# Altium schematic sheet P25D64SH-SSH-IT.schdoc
size 127 x 101 mm
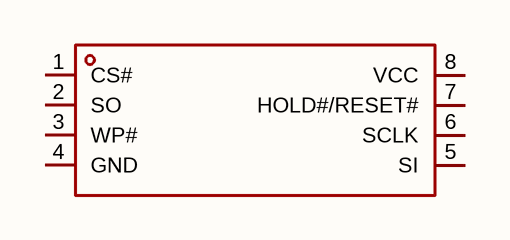
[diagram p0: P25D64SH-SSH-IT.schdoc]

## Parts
U?  p25d64sh-ssh-it  [SOP-8_L4.9-W3.9-P1.27-LS6.0-BL]  (value not drawn)

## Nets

Not connected (* = marked no-connect by the designer): U? 1(CS#) 2(SO) 3(WP#) 4(GND) 5(SI) 6(SCLK) 7(HOLD#/RESET#) 8(VCC)

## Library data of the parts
U? = p25d64sh-ssh-it: 接口类型:SPI;存储容量:64Mbit;时钟频率(fc):120MHz;; Manufacturer: PUYA(普冉); AddInBom: yes; ModelId: 75c24a7891ee4dd6bdac16a7163ff87e; ModelName: SOP-8_L4.9-W3.9-P1.27-LS6.0-BL-1; ModelTransform: 192.913,236.22,0,0,0,0,-0.393,2.749,0; Interface: SPI; Memory Size: 64Mbit; Clock Frequency: 120MHz; Voltage - Supply: 2.3V~3.6V; Standby Supply Current: 10uA; Program / Erase Cycles: 100000次; Write Cycle Time (tWC): 8ms; Page Programming Time (Tpp): 2ms; Block Erase Time(tBE): 16ms; Data Retention - TDR (Year): 10年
